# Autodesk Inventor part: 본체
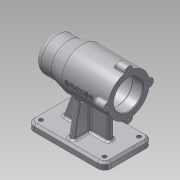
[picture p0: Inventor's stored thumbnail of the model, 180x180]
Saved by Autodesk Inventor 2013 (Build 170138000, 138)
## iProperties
Created: 2019-07
Part Number: 본체
Material: 알루미늄 6061
Document SubType Name: Modeling
Designer: Administrator
Density: 2.71 g/cm^3
Mass: 649.703 g
Surface Area: 655.943 cm^2
Volume: 239.743 cm^3
Author: Administrator
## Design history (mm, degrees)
sketch "스케치1"
  geometry: L1 (-56, 0)-(56, 0); L2 (-56, 0)-(-56, 15); L3 (-46, 25)-(-31, 25); L4 (-31, 25)-(-11, 30); L5 (-11, 30)-(56, 30); L6 (56, 30)-(56, 21); L7 (56, 21)-(41, 21); L8 (41, 21)-(41, 21); L9 (38, 24)-(-10, 24); L10 (-13, 21)-(-13, 21); L11 (-13, 21)-(-24.7, 21); L12 (-25, 20.7)-(-25, 17.5); L13 (-25, 17.5)-(-42.7, 17.5); L14 (-43, 17.2)-(-43, 16); L15 (-43, 16)-(-46.7, 16); L16 (-47, 15.7)-(-47, 10.5); L17 (-50, 7.5)-(-50, 0); L18 (-47, 10.5)-(-47, 10.5); L19 (-50, 0)-(-56, 0); L20 (56, 21)-(56, 0); A1 r 10 centre (-46, 15) between (-46, 25) and (-56, 15); A2 r 3 centre (-47, 7.5) between (-47, 10.5) and (-50, 7.5); A3 r 0.3 centre (-46.7, 15.7) between (-46.7, 16) and (-47, 15.7); A4 r 0.3 centre (-42.7, 17.2) between (-42.7, 17.5) and (-43, 17.2); A5 r 0.3 centre (-24.7, 20.7) between (-24.7, 21) and (-25, 20.7); A6 r 3 centre (-10, 21) between (-10, 24) and (-13, 21); A7 r 3 centre (38, 21) between (41, 21) and (38, 24); 5 further points
  constraints: 40 end point, 14 point on circle, 14 tangent, 9 parallel, 7 centre point, 7 perpendicular, 7 point on line, 4 equal radius, 2 collinear, 2 horizontal, 1 coincident, 1 midpoint
  dimensions: "d0" = 112 distance of L1.start L1.end; "d2" = 45 distance from line of L4.end L2; "d3" = 25 distance of L3.end point (-56, 25); "d4" = 60 diameter of L5 L1; "d5" = 50 diameter of L3 L1; "d6" = 15 distance of L6.end L7.end; "d7" = 42 diameter of L7 L1; "d8" = 54 distance of point (41, 24) point (-13, 24); "d9" = 48 diameter of L9 L1; "d10" = 42 diameter of L11 L1; "d11" = 12 distance between parallel lines of L12 L10; "d12" = 18 distance between parallel lines of L14 L12; "d13" = 35 diameter of L13 L1; "d14" = 32 diameter of L15 L1; "d15" = 4 distance between parallel lines of L16 L14; "d16" = 3 distance between parallel lines of L17 L16; "d17" = 21 diameter of L16.end L1; "d18" = 10 radius of A1; "d19" = 3 radius of A2; "d20" = 0.3 radius of A3
revolve "회전1" sketch "스케치1" stored, may be unused: angle "d21" = 90 deg
sketch "스케치2"
  geometry: C1 r 21 at (0, 0) reference; A1 r 30 centre (0, 0) between (5.97, 29.4) and (-5.97, 29.4) reference; A2 r 6 centre (0, 30) between (5.97, 29.4) and (-5.97, 29.4); A3 r 30 centre (0, 0) between (5.97, 29.4) and (-5.97, 29.4)
  constraints: 7 point on circle, 2 centre point, 1 vertical alignment
  dimensions: "d22" = 30 distance of C1.centre A2.centre; "d23" = 12 diameter of A2
extrude "돌출1" join sketch "스케치2" distance "d24" = 16; taper "d25" = 0 deg
sketch "스케치3"
  geometry: A1 r 6 centre (-30, -30) between (-29.4, -24.03) and (-29.4, -35.97) reference; A2 r 6 centre (0, -60) between (-5.97, -59.4) and (5.97, -59.4) reference; A3 r 6 centre (30, -30) between (29.4, -35.97) and (29.4, -24.03) reference; A4 r 6 centre (0, 0) between (5.97, -0.6) and (-5.97, -0.6) reference; 4 further points
  constraints: 4 coincident
hole "구멍1" sketch "스케치3" at (0, 0), (-30, -30), (0, -60), (30, -30) diameter "d29" = 3.242; stored, may be unused: countersink angle "d33" = 90 deg, drill point angle "d35" = 118 deg; dims "d30" = 8, "d31" = 4, "d32" = 2, "d34" = 11
sketch "스케치4"
  geometry: L1 (-56, -80)-(56, -80); L2 (56, -80)-(56, -70); L3 (56, -70)-(-56, -70); L4 (-56, -70)-(-56, -80); 2 further points
  constraints: 8 end point, 2 parallel, 1 horizontal, 1 midpoint, 1 perpendicular, 1 vertical alignment
  dimensions: "d36" = 10 distance of L1.end L2.end; "d38" = 80 distance from line of point (0, 0) L1; "d39" = 112 distance of L1.start L1.end
extrude "돌출2" join sketch "스케치4" stored distance "d40" = 70; taper "d41" = 0 deg
sketch "스케치5"
  geometry: L1 (0, 70)-(0, 0) reference; L2 (112, 70)-(112, 0) reference; L3 (0, 70)-(112, 70) reference; L4 (52, 7)-(60, 7); L5 (60, 7)-(60, 63); L6 (60, 63)-(52, 63); L7 (52, 63)-(52, 7); L8 (52, 7)-(60, 63); L9 (60, 7)-(52, 63); L10 (20, 31)-(87, 31); L11 (87, 31)-(87, 39); L12 (87, 39)-(20, 39); L13 (20, 39)-(20, 31); 3 further points
  constraints: 20 end point, 4 midpoint, 4 parallel, 2 horizontal, 2 perpendicular, 1 horizontal alignment
  dimensions: "d42" = 8 distance of L5.end L6.end; "d46" = 7 distance between parallel lines of L3 L6; "d47" = 8 distance of L12.end L10.start; "d48" = 20 distance between parallel lines of L1 L13; "d49" = 25 distance between parallel lines of L2 L11
extrude "돌출3" join sketch "스케치5" stored distance "d50" = 70; taper "d51" = 0 deg
feature "면 기울기1" dims angle "d52" = 20 deg
feature "면 기울기2" dims angle "d53" = 10 deg
feature "면 기울기3" dims angle "d54" = 10 deg
fillet "모깎기1" dims "d55" = 10
sketch "스케치6"
  geometry: A1 r 10 centre (0, 60) between (0, 70) and (-10, 60) reference; A2 r 10 centre (0, 10) between (-10, 10) and (0, 0) reference; A3 r 10 centre (92, 10) between (92, 0) and (102, 10) reference; A4 r 10 centre (92, 60) between (102, 60) and (92, 70) reference; 5 further points
  constraints: 4 coincident
hole "구멍2" sketch "스케치6" at (0, 60), (92, 60), (92, 10), (0, 10) diameter "d56" = 6; stored, may be unused: countersink angle "d60" = 90 deg, drill point angle "d62" = 118 deg; dims "d57" = 8, "d58" = 4, "d59" = 2, "d61" = 11
node "작업 평면2"
sketch "스케치7"
  geometry: L1 (33.5, 5.97)-(33.5, 29.4) reference; 2 further points
  constraints: 1 horizontal alignment, 1 other
  dimensions: "d63" = 42 distance from line of L1 point (-8.5, 0)
feature "엠보싱1" sketch "스케치7" dims "d0" = 112, "d2" = 45, "d3" = 25, "d4" = 60, "d5" = 50, "d6" = 15, "d7" = 42, "d8" = 54, "d9" = 48, "d10" = 42, "d11" = 12, "d12" = 18, "d13" = 35, "d14" = 32, "d15" = 4, "d16" = 3, "d17" = 21, "d18" = 10, "d19" = 3, "d20" = 0.3, "d64" = 0.5, "d65" = 0
fillet "모깎기2" dims "d66" = 3
fillet "모깎기3" dims "d67" = 1
fillet "모깎기4" dims "d68" = 3
fillet "모깎기5" dims "d69" = 3
fillet "모깎기6" dims "d70" = 3
chamfer "모따기1" distance "d71" = 1; stored, may be unused: second distance "d72" = 2, angle "d73" = 45 deg
chamfer "모따기2" distance "d74" = 3; stored, may be unused: second distance "d75" = 2, angle "d76" = 45 deg
node "솔리드1"
pattern_circular "원형 패턴1" dims angle "d27" = 360 deg
